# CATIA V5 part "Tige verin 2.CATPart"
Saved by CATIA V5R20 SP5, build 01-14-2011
Part number: Tige verin 2
Bounding box of the stored display mesh (mm): x -279.999 to -219.677, y -112.16 to 9.999, z -25 to 25
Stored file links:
  U:\CFAO\Thinkmotion\Tige verin 2.CATPart
  U:\CFAO\Thinkmotion\Bras Articule.CATProduct
  U:\CFAO\Thinkmotion\Squelette Tige verin 2.CATPart
  J:\Projet Thinkmotion\areckea\Corps verin 2.CATPart
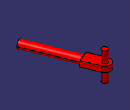
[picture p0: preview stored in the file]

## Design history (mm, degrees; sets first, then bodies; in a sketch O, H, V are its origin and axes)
Set1
  Plane1: linked copy from another document
  Point1: linked copy from another document
  Line1: linked copy from another document
Body1 (main body)
  Sketch1 on Plane1, origin (0, 0, 0), H (1, 0, 0), V (0, 1, 0)
    circle A1 centre (-270, 0) radius 5
    point P1 (-270, 0)
    reference projected point E1 (-270, 0) from Point1
    radius A1 = 5
    coincidence: P1 H
    concentricity: A1 E1
  Pad1: profile Sketch1, direction (0, 0, 1), length 25, mirrored extent
  Sketch2 on Plane1, origin (0, 0, 0), H (1, 0, 0), V (0, 1, 0)
    line L1 (-249.5735, -24.1404) -> (-260.7152, 3.7139)
    arc A1 centre (-270, 0) radius 10 from (-260.7152, 3.7139) to (-279.2848, -3.7139) ccw
    line L2 (-279.2848, -3.7139) -> (-268.143, -31.5682)
    line L3 (-268.143, -31.5682) -> (-249.5735, -24.1404)
    reference projected point E1 (-270, 0) from Point1
    reference projected line E2 (-270, 0) -> (-255.7086, -35.7285) from Line1
    reference projected line E3 (-270, 0) -> (-255.7086, -35.7285) from Line1
    reference projected point E4 (-270, 0) from Point1
    radius A1 = 10
    distance L3 E4 = 30
    tangency: A1 L1, L2 A1
    perpendicularity: L3 L1
    concentricity: A1 E1
    symmetry: L1 L2 E2
    parallelism: L1 L2, L2 E3
  Pad2: profile Sketch2, direction (0, 0, 1), length 5, mirrored extent
  Sketch3 on face of Pad2 from Sketch2.L3, origin (-26.0997, 65.2491, 0), H (0.9285, 0.3714, 0), V (0, 0, 1)
    circle A1 centre (-250.6887, 0) radius 7
    point P1 (-250.6887, 0)
    reference projected line E1 (-240.6887, -5) -> (-240.6887, 5) from edge [face of Pad2 from Sketch2.L1 | face of Pad2 from Sketch2.L3]
    radius A1 = 7
    distance A1 E1 = 3
    coincidence: P1 H
  Pad3: profile Sketch3, direction (0.3714, -0.9285, 0), length 88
